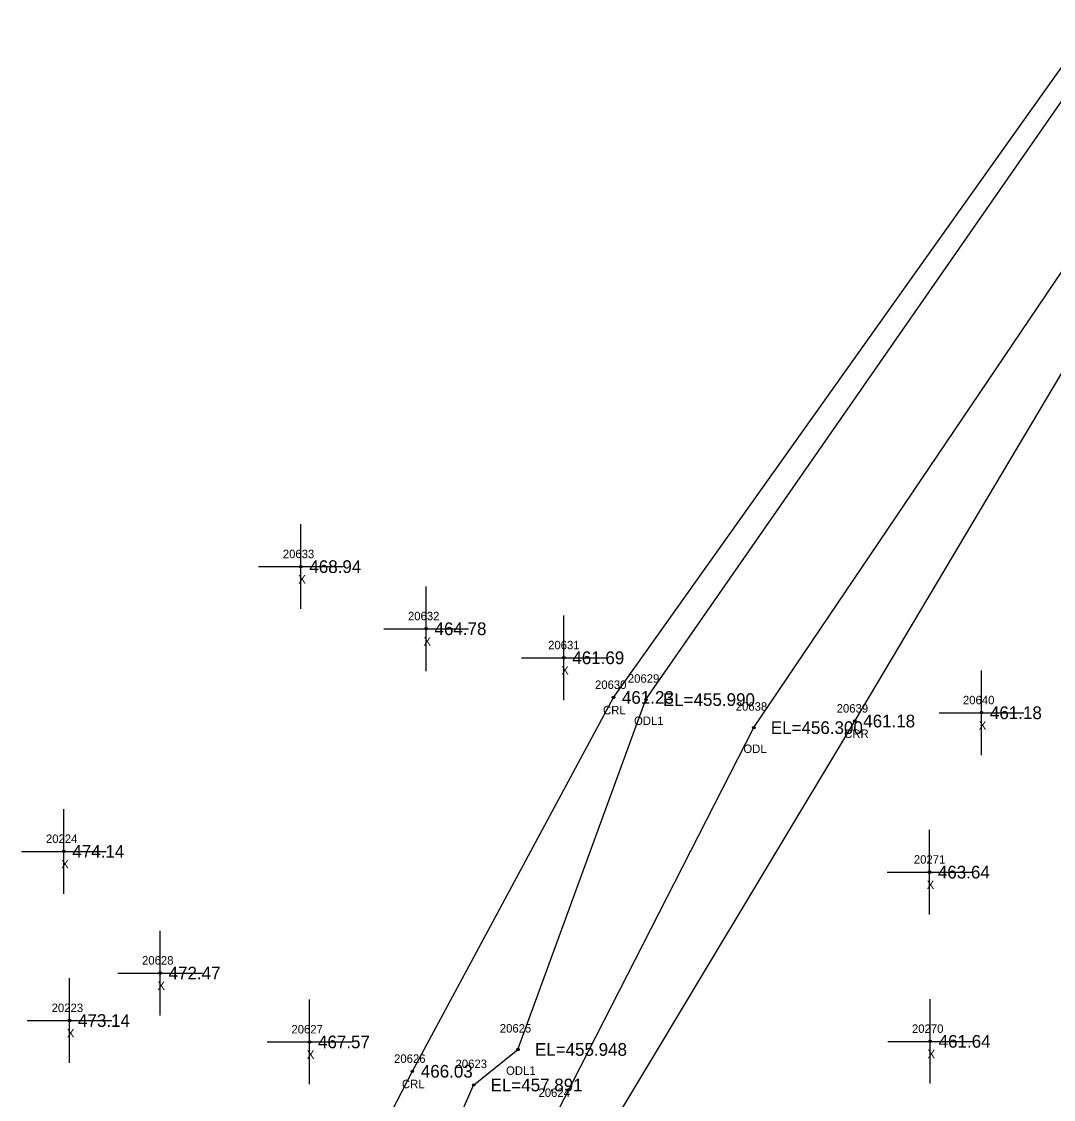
# Model space of a CAD drawing. Extents: x 1785066 to 1786589, y 770293 to 771312.
# Drawn here: x 1785771.3 to 1785893.3, y 770930.8 to 771058.2 of the extents above; entities that cross this region are included whole.
import ezdxf

# ---------------------------------------------------------------- set-up
doc = ezdxf.new("R2010")
doc.units = 0
for name, color, linetype in [('RD_EX_H2O', 7, 'Continuous'), ('RD_EX_H2O_txCode', 7, 'Continuous'), ('RD_EX_Misc', 7, 'Continuous'), ('RD_EX_Misc_txCode', 7, 'Continuous'), ('RD_EX_TX_H2O_ELEV', 7, 'Continuous'), ('RD_EX_TX_Misc_ELEV', 7, 'Continuous'), ('RD_SMD_Locator', 7, 'Continuous')]:
    doc.layers.add(name, color=color, linetype=linetype)

msp = doc.modelspace()

# ---------------------------------------------------------------- linework, layer by layer
at = {"layer": 'RD_EX_H2O'}
for points in [[(1785796.94, 770894.21), (1785817.52, 770934.08), (1785841.28, 770978.27), (1785905.84, 771069.13), (1785934.06, 771107.4), (1785932.74, 771138.87), (1785957.1, 771183.16), (1785993.97, 771208.54), (1785990.48, 771236.16), (1786004.55, 771296.27)], [(1785809.1, 770721.92), (1785797.13, 770787.08), (1785799.71, 770830.45), (1785797.84, 770854.32), (1785797.31, 770871.66), (1785799.74, 770882.87), (1785807.79, 770893.6), (1785824.76, 770932.46), (1785830, 770936.66), (1785845.12, 770978.01), (1785907.84, 771068.37), (1785939.25, 771107.77), (1785943.33, 771137.21), (1785960.57, 771178.58), (1785995.85, 771206.75), (1786007.06, 771230.75), (1786010.67, 771288.67)], [(1785820.66, 770730.64), (1785814.87, 770787.58), (1785810.48, 770814.19), (1785812.13, 770827.02), (1785814.82, 770830.33), (1785807.38, 770854.48), (1785804.49, 770870.81), (1785818.14, 770890.97), (1785834.56, 770929.05), (1785857.87, 770974.7), (1785917.08, 771062.46), (1785943.86, 771096.04), (1785952.84, 771134.11), (1785966.16, 771175.54), (1786004.33, 771202.23), (1786012.95, 771230.11), (1786017.56, 771287.45)], [(1785823.91, 770890.02), (1785840.03, 770925.86), (1785869.79, 770975.48), (1785920.39, 771060.62), (1785947.12, 771092.26), (1785958.51, 771131.14), (1785974.06, 771169.93), (1786009.64, 771197.71), (1786027.99, 771233.04), (1786021.73, 771286.51)]]:
    msp.add_lwpolyline(points, dxfattribs=at)
at = {"layer": 'RD_EX_Misc'}
for p, q in [((1785804.35, 770988.73), (1785804.35, 770998.73)), ((1785799.35, 770993.73), (1785809.35, 770993.73)), ((1785819.14, 770981.39), (1785819.14, 770991.39)), ((1785835.42, 770977.96), (1785835.42, 770987.96)), ((1785814.14, 770986.39), (1785824.14, 770986.39)), ((1785830.42, 770982.96), (1785840.42, 770982.96)), ((1785884.76, 770971.46), (1785884.76, 770981.46)), ((1785879.76, 770976.46), (1785889.76, 770976.46)), ((1785776.35, 770955.07), (1785776.35, 770965.07)), ((1785878.61, 770952.62), (1785878.61, 770962.62)), ((1785771.35, 770960.07), (1785781.35, 770960.07)), ((1785873.61, 770957.62), (1785883.61, 770957.62)), ((1785787.72, 770940.69), (1785787.72, 770950.69)), ((1785777.02, 770935.08), (1785777.02, 770945.08)), ((1785782.72, 770945.69), (1785792.72, 770945.69)), ((1785805.37, 770932.55), (1785805.37, 770942.55)), ((1785878.7, 770932.62), (1785878.7, 770942.62)), ((1785772.02, 770940.08), (1785782.02, 770940.08)), ((1785800.37, 770937.55), (1785810.37, 770937.55)), ((1785873.7, 770937.62), (1785883.7, 770937.62))]:
    msp.add_line(p, q, dxfattribs=at)
at = {"layer": 'RD_SMD_Locator'}
for centre in [(1785804.35, 770993.73), (1785819.14, 770986.39), (1785835.42, 770982.96), (1785841.28, 770978.27), (1785845.12, 770978.01), (1785869.79, 770975.48), (1785884.76, 770976.46), (1785857.87, 770974.7), (1785776.35, 770960.07), (1785878.61, 770957.62), (1785787.72, 770945.69), (1785777.02, 770940.08), (1785805.37, 770937.55), (1785878.7, 770937.62), (1785830, 770936.66), (1785817.52, 770934.08), (1785824.76, 770932.46)]:
    msp.add_circle(centre, 0.15, dxfattribs=at)

# ---------------------------------------------------------------- texts
at = {"layer": 'RD_EX_H2O_txCode'}
for s, p in [('20629', (1785842.98, 770980.01)), ('20630', (1785839.1, 770979.27)), ('CRL', (1785840.05, 770976.27)), ('20638', (1785855.73, 770976.7)), ('20639', (1785867.65, 770976.48)), ('ODL1', (1785843.71, 770975.01)), ('CRR', (1785868.54, 770973.48)), ('ODL', (1785856.63, 770971.7)), ('20625', (1785827.85, 770938.66)), ('20626', (1785815.36, 770935.08)), ('20623', (1785822.62, 770934.46)), ('ODL1', (1785828.59, 770933.66)), ('CRL', (1785816.29, 770932.08)), ('20624', (1785832.42, 770931.05))]:
    msp.add_text(s, height=1, dxfattribs=at).set_placement(p)
at = {"layer": 'RD_EX_Misc_txCode'}
for s, p in [('20633', (1785802.21, 770994.73)), ('X', (1785804.04, 770991.73)), ('20632', (1785817, 770987.39)), ('X', (1785818.83, 770984.39)), ('20631', (1785833.56, 770983.96)), ('X', (1785835.11, 770980.96)), ('20640', (1785882.57, 770977.46)), ('X', (1785884.44, 770974.46)), ('20224', (1785774.23, 770961.07)), ('X', (1785776.03, 770958.07)), ('20271', (1785876.77, 770958.62)), ('X', (1785878.29, 770955.62)), ('20628', (1785785.58, 770946.69)), ('X', (1785787.4, 770943.69)), ('20223', (1785774.9, 770941.08)), ('X', (1785776.7, 770938.08)), ('20627', (1785803.23, 770938.55)), ('20270', (1785876.55, 770938.62)), ('X', (1785805.05, 770935.55)), ('X', (1785878.39, 770935.62))]:
    msp.add_text(s, height=1, dxfattribs=at).set_placement(p)
at = {"layer": 'RD_EX_TX_H2O_ELEV'}
for s, p in [('461.23', (1785842.28, 770977.52)), ('EL=455.990', (1785847.12, 770977.26)), ('461.18', (1785870.79, 770974.73)), ('EL=456.300', (1785859.87, 770973.95)), ('EL=455.948', (1785832, 770935.91)), ('466.03', (1785818.52, 770933.33)), ('EL=457.891', (1785826.76, 770931.71))]:
    msp.add_text(s, height=1.5, dxfattribs=at).set_placement(p)
at = {"layer": 'RD_EX_TX_Misc_ELEV'}
for s, p in [('468.94', (1785805.35, 770992.98)), ('464.78', (1785820.14, 770985.64)), ('461.69', (1785836.42, 770982.21)), ('461.18', (1785885.76, 770975.71)), ('474.14', (1785777.35, 770959.32)), ('463.64', (1785879.61, 770956.87)), ('472.47', (1785788.72, 770944.94)), ('473.14', (1785778.02, 770939.33)), ('467.57', (1785806.37, 770936.8)), ('461.64', (1785879.7, 770936.87))]:
    msp.add_text(s, height=1.5, dxfattribs=at).set_placement(p)

doc.saveas('drawing.dxf')
